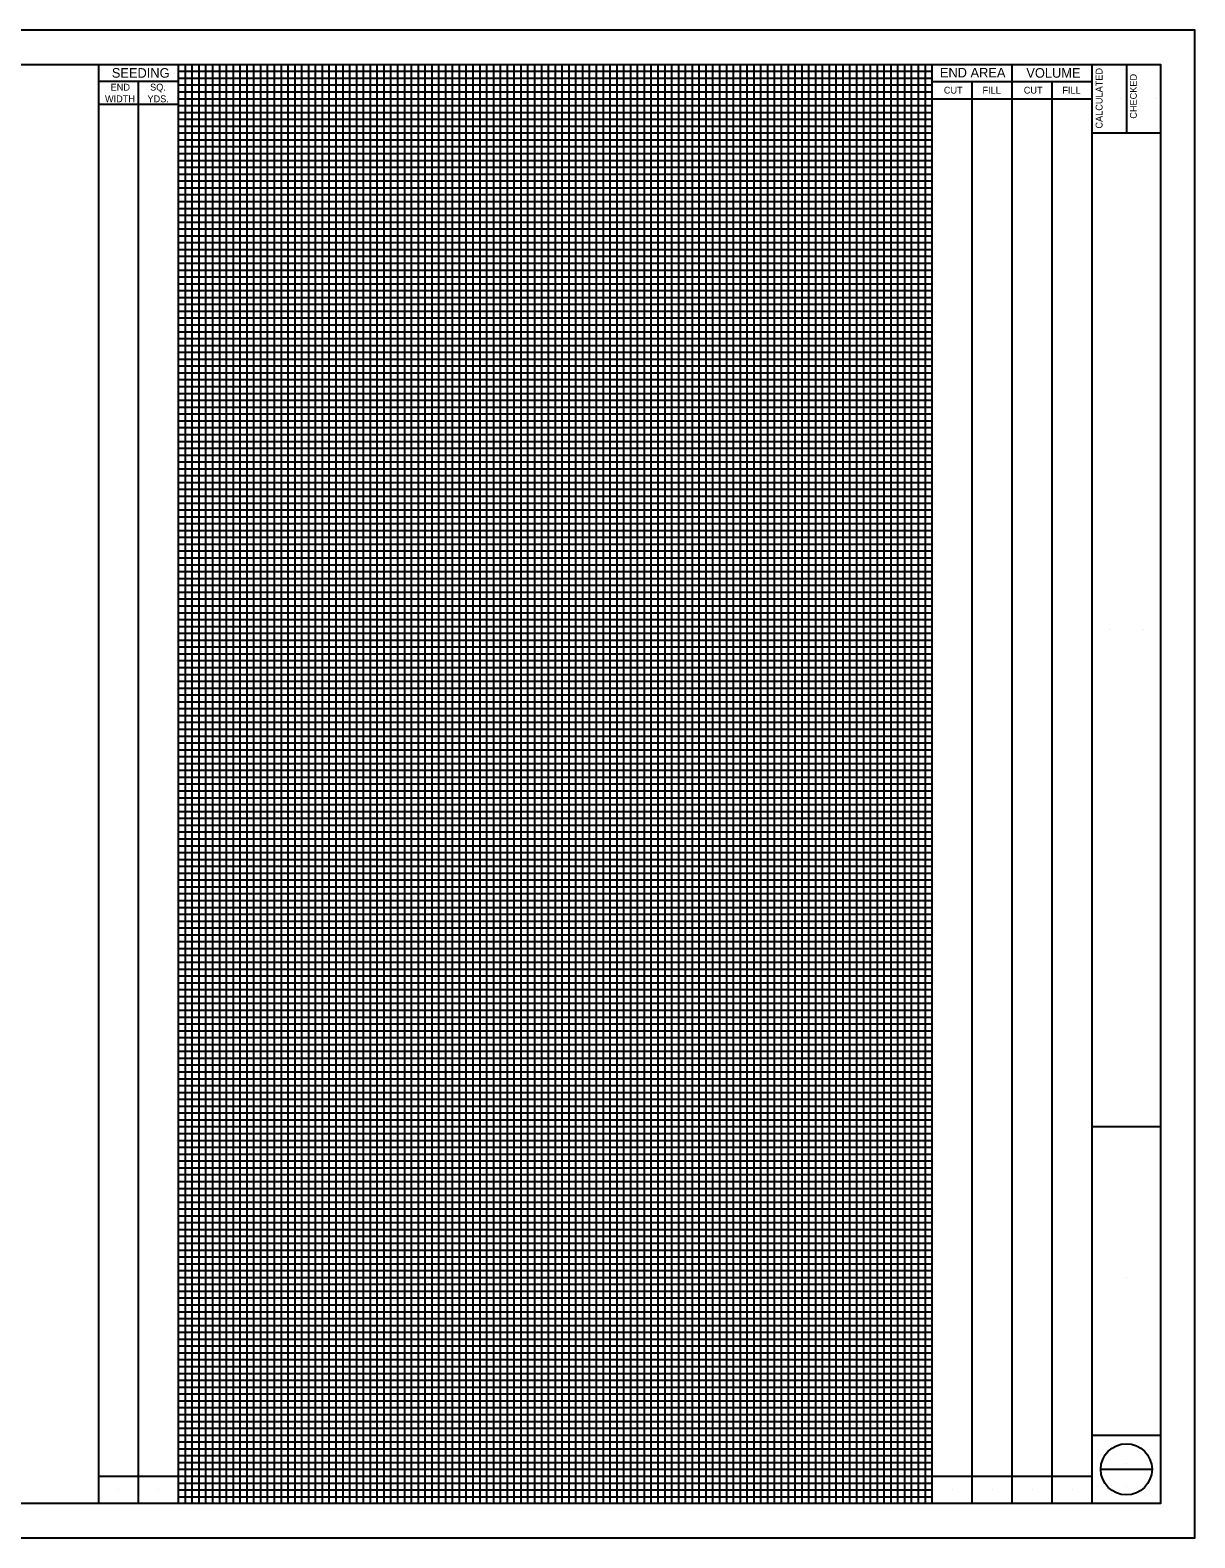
# Model space of a CAD drawing. Extents: x -16 to 154, y 112 to 222.
# Drawn here: x 69.2 to 154.2, y 112.5 to 222.5 of the extents above; entities that cross this region are included whole.
import ezdxf

# ---------------------------------------------------------------- set-up
doc = ezdxf.new("R2010")
doc.units = 0
for name, color, linetype in [('SH_Major_Grid_Line', 7, 'Continuous'), ('XS_P_Annotation', 7, 'Continuous'), ('XS_P_Boundary', 7, 'Continuous'), ('XS_P_Finished_Grade', 7, 'Continuous'), ('XS_X_Ground_Line', 7, 'Continuous')]:
    doc.layers.add(name, color=color, linetype=linetype)

msp = doc.modelspace()

# ---------------------------------------------------------------- linework, layer by layer
at = {"layer": 'SH_Major_Grid_Line'}
for p, q in [((85, 115), (85, 220)), ((90, 115), (90, 220)), ((95, 115), (95, 220)), ((100, 115), (100, 220)), ((105, 115), (105, 220)), ((110, 115), (110, 220)), ((115, 115), (115, 220)), ((120, 115), (120, 220)), ((125, 115), (125, 220)), ((130, 115), (130, 220)), ((80, 215), (135, 215)), ((80, 210), (135, 210)), ((80, 205), (135, 205)), ((80, 200), (135, 200)), ((80, 195), (135, 195)), ((80, 190), (135, 190)), ((80, 185), (135, 185)), ((80, 180), (135, 180)), ((80, 175), (135, 175)), ((80, 170), (135, 170)), ((80, 165), (135, 165)), ((80, 160), (135, 160)), ((80, 155), (135, 155)), ((80, 150), (135, 150)), ((80, 145), (135, 145)), ((80, 140), (135, 140)), ((80, 135), (135, 135)), ((80, 130), (135, 130)), ((80, 125), (135, 125)), ((80, 120), (135, 120))]:
    msp.add_line(p, q, dxfattribs=at)
at = {"layer": 'XS_P_Annotation'}
for p, q in [((146.67, 115), (146.67, 220)), ((149.17, 220), (149.17, 215)), ((146.67, 215), (151.67, 215)), ((146.67, 142.5), (151.67, 142.5)), ((146.67, 120), (151.67, 120))]:
    msp.add_line(p, q, dxfattribs=at)
msp.add_lwpolyline([(-5.83, 220), (151.67, 220), (151.67, 115), (-5.83, 115)], close=True, dxfattribs=at)
at = {"layer": 'XS_P_Boundary'}
for p, q in [((80, 219.5), (135, 219.5)), ((80, 219), (135, 219)), ((80.5, 115), (80.5, 220)), ((81, 115), (81, 220)), ((81.5, 115), (81.5, 220)), ((82, 115), (82, 220)), ((82.5, 115), (82.5, 220)), ((83, 115), (83, 220)), ((83.5, 115), (83.5, 220)), ((84, 115), (84, 220)), ((84.5, 115), (84.5, 220)), ((85.5, 115), (85.5, 220)), ((86, 115), (86, 220)), ((86.5, 115), (86.5, 220)), ((87, 115), (87, 220)), ((87.5, 115), (87.5, 220)), ((88, 115), (88, 220)), ((88.5, 115), (88.5, 220)), ((89, 115), (89, 220)), ((89.5, 115), (89.5, 220)), ((90.5, 115), (90.5, 220)), ((91, 115), (91, 220)), ((91.5, 115), (91.5, 220)), ((92, 115), (92, 220)), ((92.5, 115), (92.5, 220)), ((93, 115), (93, 220)), ((93.5, 115), (93.5, 220)), ((94, 115), (94, 220)), ((94.5, 115), (94.5, 220)), ((95.5, 115), (95.5, 220)), ((96, 115), (96, 220)), ((96.5, 115), (96.5, 220)), ((97, 115), (97, 220)), ((97.5, 115), (97.5, 220)), ((98, 115), (98, 220)), ((98.5, 115), (98.5, 220)), ((99, 115), (99, 220)), ((99.5, 115), (99.5, 220)), ((100.5, 115), (100.5, 220)), ((101, 115), (101, 220)), ((101.5, 115), (101.5, 220)), ((102, 115), (102, 220)), ((102.5, 115), (102.5, 220)), ((103, 115), (103, 220)), ((103.5, 115), (103.5, 220)), ((104, 115), (104, 220)), ((104.5, 115), (104.5, 220)), ((105.5, 115), (105.5, 220)), ((106, 115), (106, 220)), ((106.5, 115), (106.5, 220)), ((107, 115), (107, 220)), ((107.5, 115), (107.5, 220)), ((108, 115), (108, 220)), ((108.5, 115), (108.5, 220)), ((109, 115), (109, 220)), ((109.5, 115), (109.5, 220)), ((110.5, 115), (110.5, 220)), ((111, 115), (111, 220)), ((111.5, 115), (111.5, 220)), ((112, 115), (112, 220)), ((112.5, 115), (112.5, 220)), ((113, 115), (113, 220)), ((113.5, 115), (113.5, 220)), ((114, 115), (114, 220)), ((114.5, 115), (114.5, 220)), ((115.5, 115), (115.5, 220)), ((116, 115), (116, 220)), ((116.5, 115), (116.5, 220)), ((117, 115), (117, 220)), ((117.5, 115), (117.5, 220)), ((118, 115), (118, 220)), ((118.5, 115), (118.5, 220)), ((119, 115), (119, 220)), ((119.5, 115), (119.5, 220)), ((120.5, 115), (120.5, 220)), ((121, 115), (121, 220)), ((121.5, 115), (121.5, 220)), ((122, 115), (122, 220)), ((122.5, 115), (122.5, 220)), ((123, 115), (123, 220)), ((123.5, 115), (123.5, 220)), ((124, 115), (124, 220)), ((124.5, 115), (124.5, 220)), ((125.5, 115), (125.5, 220)), ((126, 115), (126, 220)), ((126.5, 115), (126.5, 220)), ((127, 115), (127, 220)), ((127.5, 115), (127.5, 220)), ((128, 115), (128, 220)), ((128.5, 115), (128.5, 220)), ((129, 115), (129, 220)), ((129.5, 115), (129.5, 220)), ((130.5, 115), (130.5, 220)), ((131, 115), (131, 220)), ((131.5, 115), (131.5, 220)), ((132, 115), (132, 220)), ((132.5, 115), (132.5, 220)), ((133, 115), (133, 220)), ((133.5, 115), (133.5, 220)), ((134, 115), (134, 220)), ((134.5, 115), (134.5, 220)), ((80, 218.5), (135, 218.5)), ((80, 218), (135, 218)), ((80, 217.5), (135, 217.5)), ((80, 217), (135, 217)), ((80, 216.5), (135, 216.5)), ((80, 216), (135, 216)), ((80, 215.5), (135, 215.5)), ((80, 214.5), (135, 214.5)), ((80, 214), (135, 214)), ((80, 213.5), (135, 213.5)), ((80, 213), (135, 213)), ((80, 212.5), (135, 212.5)), ((80, 212), (135, 212)), ((80, 211.5), (135, 211.5)), ((80, 211), (135, 211)), ((80, 210.5), (135, 210.5)), ((80, 209.5), (135, 209.5)), ((80, 209), (135, 209)), ((80, 208.5), (135, 208.5)), ((80, 208), (135, 208)), ((80, 207.5), (135, 207.5)), ((80, 207), (135, 207)), ((80, 206.5), (135, 206.5)), ((80, 206), (135, 206)), ((80, 205.5), (135, 205.5)), ((80, 204.5), (135, 204.5)), ((80, 204), (135, 204)), ((80, 203.5), (135, 203.5)), ((80, 203), (135, 203)), ((80, 202.5), (135, 202.5)), ((80, 202), (135, 202)), ((80, 201.5), (135, 201.5)), ((80, 201), (135, 201)), ((80, 200.5), (135, 200.5)), ((80, 199.5), (135, 199.5)), ((80, 199), (135, 199)), ((80, 198.5), (135, 198.5)), ((80, 198), (135, 198)), ((80, 197.5), (135, 197.5)), ((80, 197), (135, 197)), ((80, 196.5), (135, 196.5)), ((80, 196), (135, 196)), ((80, 195.5), (135, 195.5)), ((80, 194.5), (135, 194.5)), ((80, 194), (135, 194)), ((80, 193.5), (135, 193.5)), ((80, 193), (135, 193)), ((80, 192.5), (135, 192.5)), ((80, 192), (135, 192)), ((80, 191.5), (135, 191.5)), ((80, 191), (135, 191)), ((80, 190.5), (135, 190.5)), ((80, 189.5), (135, 189.5)), ((80, 189), (135, 189)), ((80, 188.5), (135, 188.5)), ((80, 188), (135, 188)), ((80, 187.5), (135, 187.5)), ((80, 187), (135, 187)), ((80, 186.5), (135, 186.5)), ((80, 186), (135, 186)), ((80, 185.5), (135, 185.5)), ((80, 184.5), (135, 184.5)), ((80, 184), (135, 184)), ((80, 183.5), (135, 183.5)), ((80, 183), (135, 183)), ((80, 182.5), (135, 182.5)), ((80, 182), (135, 182)), ((80, 181.5), (135, 181.5)), ((80, 181), (135, 181)), ((80, 180.5), (135, 180.5)), ((80, 179.5), (135, 179.5)), ((80, 179), (135, 179)), ((80, 178.5), (135, 178.5)), ((80, 178), (135, 178)), ((80, 177.5), (135, 177.5)), ((80, 177), (135, 177)), ((80, 176.5), (135, 176.5)), ((80, 176), (135, 176)), ((80, 175.5), (135, 175.5)), ((80, 174.5), (135, 174.5)), ((80, 174), (135, 174)), ((80, 173.5), (135, 173.5)), ((80, 173), (135, 173)), ((80, 172.5), (135, 172.5)), ((80, 172), (135, 172)), ((80, 171.5), (135, 171.5)), ((80, 171), (135, 171)), ((80, 170.5), (135, 170.5)), ((80, 169.5), (135, 169.5)), ((80, 169), (135, 169)), ((80, 168.5), (135, 168.5)), ((80, 168), (135, 168)), ((80, 167.5), (135, 167.5)), ((80, 167), (135, 167)), ((80, 166.5), (135, 166.5)), ((80, 166), (135, 166)), ((80, 165.5), (135, 165.5)), ((80, 164.5), (135, 164.5)), ((80, 164), (135, 164)), ((80, 163.5), (135, 163.5)), ((80, 163), (135, 163)), ((80, 162.5), (135, 162.5)), ((80, 162), (135, 162)), ((80, 161.5), (135, 161.5)), ((80, 161), (135, 161)), ((80, 160.5), (135, 160.5)), ((80, 159.5), (135, 159.5)), ((80, 159), (135, 159)), ((80, 158.5), (135, 158.5)), ((80, 158), (135, 158)), ((80, 157.5), (135, 157.5)), ((80, 157), (135, 157)), ((80, 156.5), (135, 156.5)), ((80, 156), (135, 156)), ((80, 155.5), (135, 155.5)), ((80, 154.5), (135, 154.5)), ((80, 154), (135, 154)), ((80, 153.5), (135, 153.5)), ((80, 153), (135, 153)), ((80, 152.5), (135, 152.5)), ((80, 152), (135, 152)), ((80, 151.5), (135, 151.5)), ((80, 151), (135, 151)), ((80, 150.5), (135, 150.5)), ((80, 149.5), (135, 149.5)), ((80, 149), (135, 149)), ((80, 148.5), (135, 148.5)), ((80, 148), (135, 148)), ((80, 147.5), (135, 147.5)), ((80, 147), (135, 147)), ((80, 146.5), (135, 146.5)), ((80, 146), (135, 146)), ((80, 145.5), (135, 145.5)), ((80, 144.5), (135, 144.5)), ((80, 144), (135, 144)), ((80, 143.5), (135, 143.5)), ((80, 143), (135, 143)), ((80, 142.5), (135, 142.5)), ((80, 142), (135, 142)), ((80, 141.5), (135, 141.5)), ((80, 141), (135, 141)), ((80, 140.5), (135, 140.5)), ((80, 139.5), (135, 139.5)), ((80, 139), (135, 139)), ((80, 138.5), (135, 138.5)), ((80, 138), (135, 138)), ((80, 137.5), (135, 137.5)), ((80, 137), (135, 137)), ((80, 136.5), (135, 136.5)), ((80, 136), (135, 136)), ((80, 135.5), (135, 135.5)), ((80, 134.5), (135, 134.5)), ((80, 134), (135, 134)), ((80, 133.5), (135, 133.5)), ((80, 133), (135, 133)), ((80, 132.5), (135, 132.5)), ((80, 132), (135, 132)), ((80, 131.5), (135, 131.5)), ((80, 131), (135, 131)), ((80, 130.5), (135, 130.5)), ((80, 129.5), (135, 129.5)), ((80, 129), (135, 129)), ((80, 128.5), (135, 128.5)), ((80, 128), (135, 128)), ((80, 127.5), (135, 127.5)), ((80, 127), (135, 127)), ((80, 126.5), (135, 126.5)), ((80, 126), (135, 126)), ((80, 125.5), (135, 125.5)), ((80, 124.5), (135, 124.5)), ((80, 124), (135, 124)), ((80, 123.5), (135, 123.5)), ((80, 123), (135, 123)), ((80, 122.5), (135, 122.5)), ((80, 122), (135, 122)), ((80, 121.5), (135, 121.5)), ((80, 121), (135, 121)), ((80, 120.5), (135, 120.5)), ((80, 119.5), (135, 119.5)), ((80, 119), (135, 119)), ((80, 118.5), (135, 118.5)), ((80, 118), (135, 118)), ((80, 117.5), (135, 117.5)), ((80, 117), (135, 117)), ((80, 116.5), (135, 116.5)), ((80, 116), (135, 116)), ((80, 115.5), (135, 115.5))]:
    msp.add_line(p, q, dxfattribs=at)
at = {"layer": 'XS_P_Finished_Grade'}
msp.add_lwpolyline([(-15.83, 112.5), (154.17, 112.5), (154.17, 222.5), (-15.83, 222.5)], close=True, dxfattribs=at)
at = {"layer": 'XS_X_Ground_Line'}
for p, q in [((74.17, 115), (74.17, 220)), ((80, 115), (80, 220)), ((135, 115), (135, 220)), ((140.83, 115), (140.83, 220)), ((80, 218.75), (74.17, 218.75)), ((77.08, 115), (77.08, 218.75)), ((135, 218.75), (146.67, 218.75)), ((137.92, 115), (137.92, 218.75)), ((143.75, 115), (143.75, 218.75)), ((80, 217.08), (74.17, 217.08)), ((135, 217.5), (146.67, 217.5)), ((148.77, 217.52), (148.77, 217.52)), ((151.27, 217.52), (151.27, 217.52)), ((147.92, 178.75), (147.92, 178.75)), ((150.43, 178.75), (150.43, 178.75)), ((149.17, 131.46), (149.17, 131.46)), ((149.17, 117.92), (149.17, 117.92)), ((74.17, 117), (80, 117)), ((135, 117), (146.67, 117)), ((147.29, 117.5), (151.04, 117.5)), ((75.63, 116.03), (75.63, 116.03)), ((78.54, 116.03), (78.54, 116.03)), ((136.46, 116), (136.46, 116)), ((139.38, 116), (139.38, 116)), ((142.29, 116), (142.29, 116)), ((145.21, 116), (145.21, 116)), ((149.17, 116.22), (149.17, 116.22))]:
    msp.add_line(p, q, dxfattribs=at)
msp.add_circle((149.17, 117.5), 1.87, dxfattribs=at)

# ---------------------------------------------------------------- texts
for s, height, p in [('SEEDING', 0.7, (75.13, 219.03)), ('END AREA', 0.7, (135.56, 219.05)), ('VOLUME', 0.7, (141.87, 219.03)), ('END', 0.5, (75.04, 218.09)), ('SQ.', 0.5, (77.92, 218.09)), ('CUT', 0.5, (135.85, 217.87)), ('FILL', 0.5, (138.67, 217.87)), ('CUT', 0.5, (141.68, 217.87)), ('FILL', 0.5, (144.5, 217.87)), ('WIDTH', 0.5, (74.63, 217.24)), ('YDS.', 0.5, (77.73, 217.24))]:
    msp.add_text(s, height=height, dxfattribs=at).set_placement(p)
for s, p in [('CALCULATED', (147.43, 215.32)), ('CHECKED', (149.93, 216.04))]:
    msp.add_text(s, height=0.5, rotation=90, dxfattribs=at).set_placement(p)

doc.saveas('drawing.dxf')
